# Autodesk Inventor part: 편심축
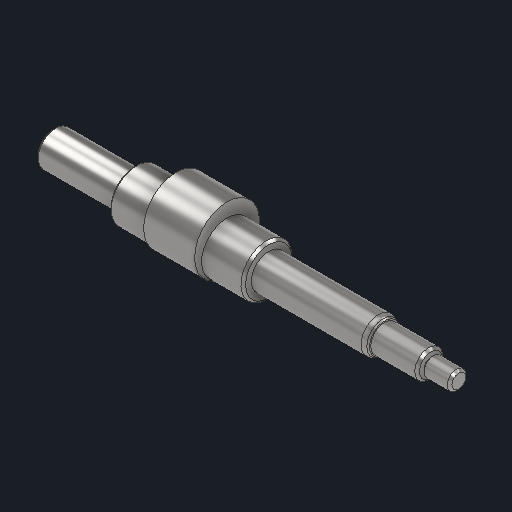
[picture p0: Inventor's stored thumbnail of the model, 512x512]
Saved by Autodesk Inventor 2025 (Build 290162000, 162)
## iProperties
Created: 2025-08
Part Number: 편심축
Material: 강철, 연강
Document SubType Name: Modeling
Designer: infra006
Density: 7.86 g/cm^3
Appearance: 기본값
Author: jhkim
Sending System: Autodesk Inventor 2026
Preprocessor: ST-DEVELOPER v20.1
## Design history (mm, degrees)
feature "솔리드1"
node "솔리드2"
